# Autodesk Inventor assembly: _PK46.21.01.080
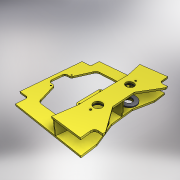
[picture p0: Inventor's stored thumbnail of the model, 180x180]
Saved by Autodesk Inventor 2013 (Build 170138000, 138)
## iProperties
Created: 2005-04
Part Number: _PK46.21.01.080
Document SubType Name: Assembly
Designer: salex
Manufacturer: Standard
Standards Organization: Custom
Author: salex
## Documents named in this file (5)
- C:\Product Design Suite 2013 Test Drive\Dynamic Simulation\Workspace\Assy, Chassis, Front\_PK46.21.01.080.iam
- C:\Product Design Suite 2013 Test Drive\Dynamic Simulation\Workspace\Assy, Chassis, Front\PK46.21.01.019.ipt
- C:\Product Design Suite 2013 Test Drive\Dynamic Simulation\Workspace\Assy, Chassis, Front\PK46.21.01.022.ipt
- C:\Product Design Suite 2013 Test Drive\Dynamic Simulation\Workspace\Assy, Chassis, Front\PK46.21.01.024.ipt
- C:\Product Design Suite 2013 Test Drive\Dynamic Simulation\Workspace\Assy, Chassis, Front\_PK46.21.01.021.ipt
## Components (9 placed, 4 different names)
1. PK46.21.01.019:1 — Совмещение:6, Совмещение:7, Вставка:1, Вставка:4, Совмещение:18, Совмещение:19, Совмещение:20, Совмещение:21, Заподлицо:3, Совмещение:22, Заподлицо:4
2. _PK46.21.01.021:1 — Совмещение:6, Совмещение:7, Вставка:2, Вставка:3, Заподлицо:1, Заподлицо:2
3. PK46.21.01.022:1 — Вставка:1
4. PK46.21.01.022:2 — Вставка:2
5. PK46.21.01.022:3 — Вставка:3
6. PK46.21.01.022:4 — Вставка:4
7. PK46.21.01.024:1 — Совмещение:20, Заподлицо:2, Совмещение:21
8. PK46.21.01.024:2 — Совмещение:18, Совмещение:19, Заподлицо:1
9. PK46.21.01.024:3 — Заподлицо:3, Совмещение:22, Заподлицо:4
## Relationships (15: Mate 7, Insert 4, Flush 4)
- Совмещение:6 [Mate]: PK46.21.01.019:1 ↔ _PK46.21.01.021:1
- Совмещение:7 [Mate]: PK46.21.01.019:1 ↔ _PK46.21.01.021:1
- Вставка:1 [Insert]: PK46.21.01.019:1 ↔ PK46.21.01.022:1
- Вставка:2 [Insert]: _PK46.21.01.021:1 ↔ PK46.21.01.022:2
- Вставка:3 [Insert]: _PK46.21.01.021:1 ↔ PK46.21.01.022:3
- Вставка:4 [Insert]: PK46.21.01.019:1 ↔ PK46.21.01.022:4
- Совмещение:18 [Mate]: PK46.21.01.019:1 ↔ PK46.21.01.024:2
- Совмещение:19 [Mate]: PK46.21.01.019:1 ↔ PK46.21.01.024:2
- Заподлицо:1 [Flush]: _PK46.21.01.021:1 ↔ PK46.21.01.024:2
- Совмещение:20 [Mate]: PK46.21.01.019:1 ↔ PK46.21.01.024:1
- Заподлицо:2 [Flush]: _PK46.21.01.021:1 ↔ PK46.21.01.024:1
- Совмещение:21 [Mate]: PK46.21.01.019:1 ↔ PK46.21.01.024:1
- Заподлицо:3 [Flush]: PK46.21.01.019:1 ↔ PK46.21.01.024:3
- Совмещение:22 [Mate]: PK46.21.01.019:1 ↔ PK46.21.01.024:3
- Заподлицо:4 [Flush]: PK46.21.01.019:1 ↔ PK46.21.01.024:3
